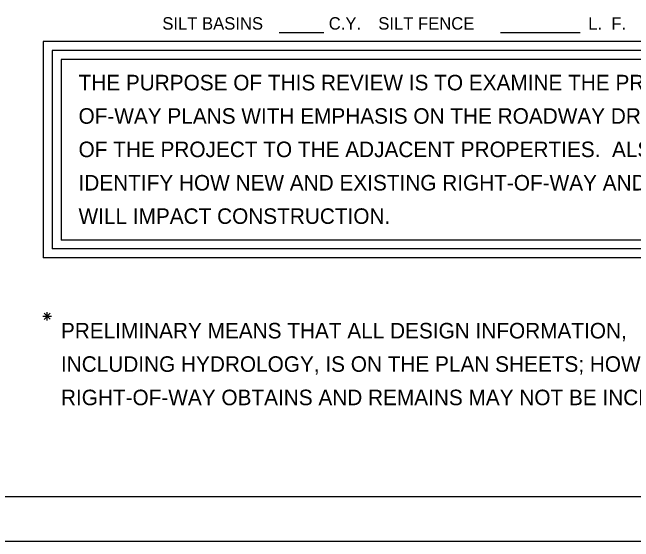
# Model space of a CAD drawing. Extents: x 8134 to 11793, y 3225 to 13425.
# Drawn here: x 11221.5 to 11569.2, y 12300 to 12596.4 of the extents above; entities that cross this region are included whole.
import ezdxf

# ---------------------------------------------------------------- set-up
doc = ezdxf.new("R2010")
doc.units = 0
for name, color, linetype in [('RD_SHT_Bndy', 7, 'Continuous'), ('RD_SHT_IplotShp', 7, 'Continuous'), ('RD_SHT_TX', 7, 'Continuous')]:
    doc.layers.add(name, color=color, linetype=linetype)

msp = doc.modelspace()

# ---------------------------------------------------------------- linework, layer by layer
at = {"layer": 'RD_SHT_Bndy'}
for p, q in [((11370.7, 12585.19), (11395.82, 12585.19)), ((11494.67, 12585.19), (11539.22, 12585.19)), ((11747.79, 12580.14), (11238.69, 12580.14)), ((11238.69, 12580.14), (11238.69, 12458.92)), ((11742.79, 12575.14), (11243.69, 12575.14)), ((11243.69, 12575.14), (11243.69, 12463.92)), ((11737.79, 12570.14), (11248.69, 12570.14)), ((11248.69, 12570.14), (11248.69, 12468.92)), ((11737.79, 12468.92), (11248.69, 12468.92)), ((11742.79, 12463.92), (11243.69, 12463.92)), ((11747.79, 12458.92), (11238.69, 12458.92)), ((11242.6, 12424.52), (11239.18, 12427.88)), ((11239.2, 12424.5), (11242.58, 12427.89)), ((11240.89, 12423.8), (11240.89, 12428.59)), ((11238.49, 12426.2), (11243.28, 12426.2)), ((11760, 12300), (10000, 12300))]:
    msp.add_line(p, q, dxfattribs=at)
msp.add_lwpolyline([(10082.45, 13375), (11757.45, 13375), (11757.45, 12325), (10082.45, 12325)], close=True, dxfattribs=at)
at = {"layer": 'RD_SHT_IplotShp'}
msp.add_lwpolyline([(9986.45, 13400), (11782.44, 13400), (11782.44, 12300), (9986.45, 12300)], close=True, dxfattribs=at)

# ---------------------------------------------------------------- texts
at = {"layer": 'RD_SHT_TX'}
for s, height, p in [('SILT BASINS', 6.9601, (11305.37, 12586.8)), ('C.Y.', 6.96, (11398.54, 12586.8)), ('SILT FENCE', 6.96, (11426.26, 12586.8)), ('L.  F.', 6.96, (11543.78, 12586.8)), ('THE PURPOSE OF THIS REVIEW IS TO EXAMINE THE PRELIMINARY RIGHT-', 8.7001, (11258.47, 12552.78)), ('OF-WAY PLANS WITH EMPHASIS ON THE ROADWAY DRAINAGE AND THE IMPACT', 8.7001, (11258.47, 12534.07)), ('OF THE PROJECT TO THE ADJACENT PROPERTIES.  ALSO THIS REVIEW WILL', 8.7001, (11258.47, 12515.37)), ('IDENTIFY HOW NEW AND EXISTING RIGHT-OF-WAY AND ROADWAY DESIGNS', 8.7001, (11258.47, 12496.67)), ('WILL IMPACT CONSTRUCTION.', 8.7001, (11258.47, 12477.97)), ('PRELIMINARY MEANS THAT ALL DESIGN INFORMATION,', 8.7001, (11248.62, 12413.8)), ('INCLUDING HYDROLOGY, IS ON THE PLAN SHEETS; HOWEVER,', 8.7001, (11248.62, 12395.1)), ('RIGHT-OF-WAY OBTAINS AND REMAINS MAY NOT BE INCLUDED.', 8.7001, (11248.62, 12376.4))]:
    msp.add_text(s, height=height, dxfattribs=at).set_placement(p)

doc.saveas('drawing.dxf')
